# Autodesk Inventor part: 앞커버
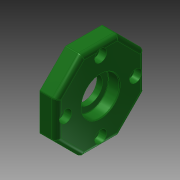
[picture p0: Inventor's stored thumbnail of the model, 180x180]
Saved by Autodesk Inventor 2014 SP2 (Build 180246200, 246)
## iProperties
Created: 2015-11
Part Number: 앞커버
Material: 알루미늄 6061
Document SubType Name: Modeling
Designer: mduedu
Density: 1 g/cm^3
Appearance: 매끄러움 - 짙은 산림 녹색
Author: mduedu
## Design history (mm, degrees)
sketch "스케치5" dims "d66" = 58
  geometry: L1 (12.012, 29)-(29, 12.012); L2 (29, 12.012)-(29, -12.012); L3 (29, -12.012)-(12.012, -29); L4 (12.012, -29)-(-12.012, -29); L5 (-12.012, -29)-(-29, -12.012); L6 (-29, -12.012)-(-29, 12.012); L7 (-29, 12.012)-(-12.012, 29); L8 (-12.012, 29)-(12.012, 29); 4 further points
  constraints: 16 end point, 2 coincident, 2 vertical alignment, 1 midpoint, 19 other
extrude "돌출2" new body sketch "스케치5" distance "d67" = 11; taper "d68" = 0 deg
sketch "스케치6"
  geometry: C1 r 16 at (0, 0); 1 further point
  constraints: 1 centre point, 1 coincident
  dimensions: "d69" = 32 diameter of C1
extrude "돌출3" join sketch "스케치6" distance "d70" = 3; taper "d71" = 0 deg
hole "구멍7" diameter "d98" = 28; stored, may be unused: countersink angle "d102" = 90 deg, drill point angle "d104" = 0 deg; dims "d99" = 6, "d100" = 4, "d101" = 2, "d103" = 3, "d145" = 10, "d146" = 10
hole "구멍8" diameter "d107" = 25; stored, may be unused: countersink angle "d111" = 90 deg, drill point angle "d113" = 0 deg; dims "d108" = 6, "d109" = 4, "d110" = 2, "d112" = 7.3, "d143" = 10, "d144" = 10
hole "구멍9" diameter "d116" = 17; stored, may be unused: countersink angle "d120" = 90 deg, drill point angle "d122" = 0 deg; dims "d114" = 10, "d115" = 10, "d117" = 6, "d118" = 4, "d119" = 2, "d121" = 7.7
chamfer "모따기2" distance "d123" = 0.6; stored, may be unused: second distance "d124" = 2, angle "d125" = 30 deg
fillet "모깎기11" dims "d126" = 0.3
fillet "모깎기12" dims "d127" = 1
fillet "모깎기13" dims "d128" = 3
fillet "모깎기14" dims "d129" = 3
fillet "모깎기15" dims "d130" = 0.3
sketch "스케치8" dims "d131" = 46
  geometry: 3 further points
  constraints: 2 vertical alignment, 1 coincident, 2 other
hole "구멍10" sketch "스케치8" at (0, 23) diameter "d132" = 4.5; stored, may be unused: countersink angle "d136" = 90 deg, drill point angle "d138" = 0 deg; dims "d133" = 6, "d134" = 8, "d135" = 4.6, "d137" = 7.7
node "솔리드2"
pattern_circular "원형 패턴4" dims angle "d140" = 360 deg
